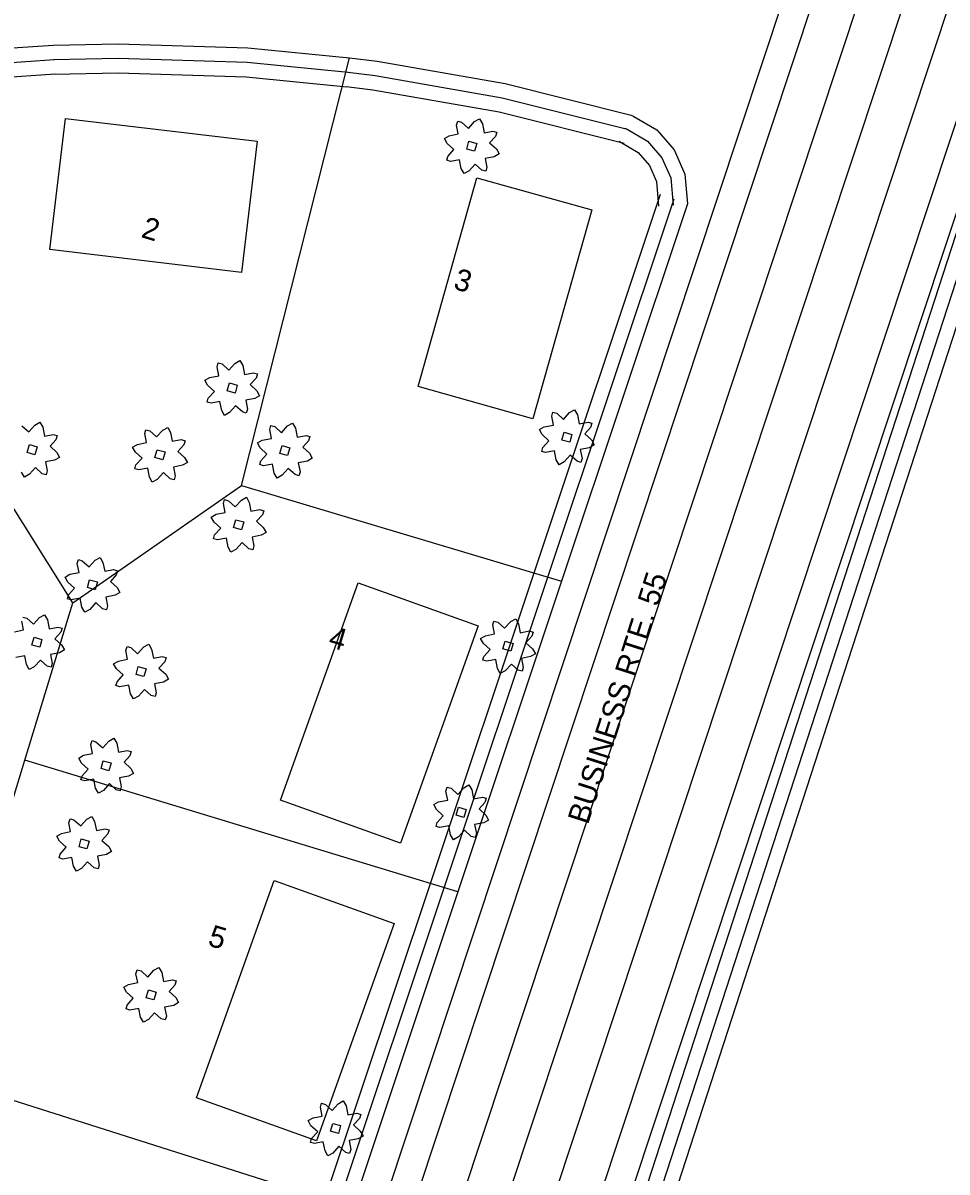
# Model space of a CAD drawing. Extents: x 1810019 to 1811399, y 1074962 to 1076105.
# Drawn here: x 1810680 to 1810935.4, y 1075531.7 to 1075849.4 of the extents above; entities that cross this region are included whole.
import ezdxf

# ---------------------------------------------------------------- set-up
doc = ezdxf.new("R2010")
doc.units = 0
for name, color, linetype in [('Environmental-New trees', 7, 'Continuous'), ('Property-Buildings', 7, 'Continuous'), ('Roadway-Centerline main', 7, 'Continuous'), ('Roadway-Edge of pavement', 7, 'Continuous'), ('Roadway-Edge of shoulder', 7, 'Continuous'), ('Roadway-Land lines', 7, 'Continuous'), ('Roadway-Sidewalks', 7, 'Continuous'), ('Text-Property owner', 7, 'Continuous'), ('Text-Route label', 7, 'Continuous')]:
    doc.layers.add(name, color=color, linetype=linetype)

msp = doc.modelspace()

# ---------------------------------------------------------------- linework, layer by layer
at = {"layer": 'Environmental-New trees'}
for points in [[(1810797.1, 1075811.43), (1810797.41, 1075812.51), (1810799.1, 1075814.37), (1810797.24, 1075816.07), (1810796.46, 1075817.45), (1810797.81, 1075818.21), (1810800.32, 1075818.71), (1810799.85, 1075821.18), (1810800.15, 1075822.26), (1810801.23, 1075821.95), (1810803.1, 1075820.26), (1810804.79, 1075822.12), (1810806.18, 1075822.9), (1810806.96, 1075821.51), (1810807.43, 1075819.04), (1810809.9, 1075819.51), (1810810.98, 1075819.21), (1810810.61, 1075818.05), (1810808.98, 1075816.26), (1810810.85, 1075814.57), (1810811.62, 1075813.18), (1810810.27, 1075812.42), (1810807.76, 1075811.93), (1810808.24, 1075809.46), (1810807.93, 1075808.38), (1810806.85, 1075808.68), (1810804.99, 1075810.38), (1810803.29, 1075808.51), (1810801.91, 1075807.74), (1810801.13, 1075809.12), (1810800.65, 1075811.6), (1810798.18, 1075811.12)], [(1810803.26, 1075816.71), (1810805.43, 1075816.1), (1810804.82, 1075813.93), (1810802.65, 1075814.54)], [(1810730.87, 1075744.59), (1810731.18, 1075745.67), (1810732.87, 1075747.53), (1810731.01, 1075749.23), (1810730.23, 1075750.62), (1810731.59, 1075751.37), (1810734.09, 1075751.87), (1810733.62, 1075754.34), (1810733.93, 1075755.42), (1810735.01, 1075755.12), (1810736.87, 1075753.42), (1810738.56, 1075755.28), (1810739.95, 1075756.06), (1810740.73, 1075754.67), (1810741.2, 1075752.2), (1810743.67, 1075752.67), (1810744.76, 1075752.37), (1810744.39, 1075751.21), (1810742.76, 1075749.42), (1810744.62, 1075747.73), (1810745.4, 1075746.34), (1810744.04, 1075745.59), (1810741.54, 1075745.09), (1810742.01, 1075742.62), (1810741.7, 1075741.54), (1810740.62, 1075741.84), (1810738.76, 1075743.54), (1810737.07, 1075741.68), (1810735.68, 1075740.9), (1810734.9, 1075742.29), (1810734.43, 1075744.76), (1810731.96, 1075744.28)], [(1810737.04, 1075749.87), (1810739.2, 1075749.26), (1810738.59, 1075747.09), (1810736.43, 1075747.7)], [(1810823.38, 1075730.96), (1810823.68, 1075732.05), (1810825.38, 1075733.91), (1810823.52, 1075735.6), (1810822.74, 1075736.99), (1810824.09, 1075737.75), (1810826.6, 1075738.24), (1810826.13, 1075740.71), (1810826.43, 1075741.79), (1810827.51, 1075741.49), (1810829.38, 1075739.8), (1810831.07, 1075741.66), (1810832.46, 1075742.43), (1810833.23, 1075741.05), (1810833.71, 1075738.58), (1810836.18, 1075739.05), (1810837.26, 1075738.74), (1810836.89, 1075737.59), (1810835.26, 1075735.8), (1810837.12, 1075734.11), (1810837.9, 1075732.72), (1810836.55, 1075731.96), (1810834.04, 1075731.47), (1810834.52, 1075728.99), (1810834.21, 1075727.91), (1810833.13, 1075728.22), (1810831.27, 1075729.91), (1810829.57, 1075728.05), (1810828.18, 1075727.27), (1810827.41, 1075728.66), (1810826.93, 1075731.13), (1810824.46, 1075730.66)], [(1810710.91, 1075726.12), (1810711.21, 1075727.2), (1810712.91, 1075729.06), (1810711.04, 1075730.76), (1810710.27, 1075732.15), (1810711.62, 1075732.9), (1810714.13, 1075733.4), (1810713.65, 1075735.87), (1810713.96, 1075736.95), (1810715.04, 1075736.65), (1810716.9, 1075734.95), (1810718.6, 1075736.81), (1810719.98, 1075737.59), (1810720.76, 1075736.2), (1810721.24, 1075733.73), (1810723.71, 1075734.2), (1810724.79, 1075733.9), (1810724.42, 1075732.74), (1810722.79, 1075730.96), (1810724.65, 1075729.26), (1810725.43, 1075727.87), (1810724.08, 1075727.12), (1810721.57, 1075726.62), (1810722.04, 1075724.15), (1810721.74, 1075723.07), (1810720.66, 1075723.37), (1810718.79, 1075725.07), (1810717.1, 1075723.21), (1810715.71, 1075722.43), (1810714.93, 1075723.82), (1810714.46, 1075726.29), (1810711.99, 1075725.81)], [(1810745.42, 1075727.28), (1810745.73, 1075728.36), (1810747.42, 1075730.22), (1810745.56, 1075731.92), (1810744.78, 1075733.3), (1810746.13, 1075734.06), (1810748.64, 1075734.55), (1810748.17, 1075737.03), (1810748.47, 1075738.11), (1810749.56, 1075737.8), (1810751.42, 1075736.11), (1810753.11, 1075737.97), (1810754.5, 1075738.75), (1810755.28, 1075737.36), (1810755.75, 1075734.89), (1810758.22, 1075735.36), (1810759.3, 1075735.06), (1810758.93, 1075733.9), (1810757.3, 1075732.11), (1810759.17, 1075730.42), (1810759.94, 1075729.03), (1810758.59, 1075728.27), (1810756.08, 1075727.78), (1810756.56, 1075725.31), (1810756.25, 1075724.23), (1810755.17, 1075724.53), (1810753.31, 1075726.22), (1810751.61, 1075724.36), (1810750.23, 1075723.59), (1810749.45, 1075724.97), (1810748.98, 1075727.45), (1810746.5, 1075726.97)], [(1810829.54, 1075736.24), (1810831.71, 1075735.63), (1810831.1, 1075733.46), (1810828.93, 1075734.07)], [(1810681.73, 1075732.81), (1810683.89, 1075732.2), (1810683.28, 1075730.03), (1810681.12, 1075730.64)], [(1810717.07, 1075731.4), (1810719.24, 1075730.79), (1810718.63, 1075728.62), (1810716.46, 1075729.23)], [(1810751.58, 1075732.56), (1810753.75, 1075731.95), (1810753.14, 1075729.78), (1810750.97, 1075730.39)], [(1810732.65, 1075706.78), (1810732.96, 1075707.86), (1810734.65, 1075709.72), (1810732.79, 1075711.42), (1810732.01, 1075712.81), (1810733.36, 1075713.56), (1810735.87, 1075714.06), (1810735.4, 1075716.53), (1810735.7, 1075717.61), (1810736.79, 1075717.31), (1810738.65, 1075715.61), (1810740.34, 1075717.47), (1810741.73, 1075718.25), (1810742.51, 1075716.86), (1810742.98, 1075714.39), (1810745.45, 1075714.86), (1810746.54, 1075714.56), (1810746.17, 1075713.4), (1810744.54, 1075711.62), (1810746.4, 1075709.92), (1810747.18, 1075708.53), (1810745.82, 1075707.78), (1810743.32, 1075707.28), (1810743.79, 1075704.81), (1810743.48, 1075703.73), (1810742.4, 1075704.03), (1810740.54, 1075705.73), (1810738.85, 1075703.87), (1810737.46, 1075703.09), (1810736.68, 1075704.48), (1810736.21, 1075706.95), (1810733.74, 1075706.48)], [(1810738.82, 1075712.06), (1810740.98, 1075711.45), (1810740.37, 1075709.28), (1810738.21, 1075709.89)], [(1810692.24, 1075690.19), (1810692.54, 1075691.27), (1810694.24, 1075693.13), (1810692.37, 1075694.82), (1810691.6, 1075696.21), (1810692.95, 1075696.97), (1810695.46, 1075697.46), (1810694.98, 1075699.93), (1810695.29, 1075701.02), (1810696.37, 1075700.71), (1810698.23, 1075699.02), (1810699.93, 1075700.88), (1810701.31, 1075701.66), (1810702.09, 1075700.27), (1810702.56, 1075697.8), (1810705.04, 1075698.27), (1810706.12, 1075697.97), (1810705.75, 1075696.81), (1810704.12, 1075695.02), (1810705.98, 1075693.33), (1810706.76, 1075691.94), (1810705.41, 1075691.18), (1810702.9, 1075690.69), (1810703.37, 1075688.22), (1810703.07, 1075687.13), (1810701.98, 1075687.44), (1810700.12, 1075689.13), (1810698.43, 1075687.27), (1810697.04, 1075686.49), (1810696.26, 1075687.88), (1810695.79, 1075690.35), (1810693.32, 1075689.88)], [(1810698.4, 1075695.46), (1810700.57, 1075694.85), (1810699.96, 1075692.69), (1810697.79, 1075693.3)], [(1810807.11, 1075673.21), (1810807.41, 1075674.29), (1810809.11, 1075676.16), (1810807.25, 1075677.85), (1810806.47, 1075679.24), (1810807.82, 1075680), (1810810.33, 1075680.49), (1810809.86, 1075682.96), (1810810.16, 1075684.04), (1810811.24, 1075683.74), (1810813.1, 1075682.04), (1810814.8, 1075683.91), (1810816.19, 1075684.68), (1810816.96, 1075683.29), (1810817.44, 1075680.82), (1810819.91, 1075681.3), (1810820.99, 1075680.99), (1810820.62, 1075679.83), (1810818.99, 1075678.05), (1810820.85, 1075676.35), (1810821.63, 1075674.97), (1810820.28, 1075674.21), (1810817.77, 1075673.71), (1810818.24, 1075671.24), (1810817.94, 1075670.16), (1810816.86, 1075670.47), (1810815, 1075672.16), (1810813.3, 1075670.3), (1810811.91, 1075669.52), (1810811.14, 1075670.91), (1810810.66, 1075673.38), (1810808.19, 1075672.91)], [(1810683.05, 1075679.58), (1810685.21, 1075678.97), (1810684.6, 1075676.8), (1810682.44, 1075677.41)], [(1810705.68, 1075666.19), (1810705.98, 1075667.27), (1810707.68, 1075669.13), (1810705.82, 1075670.83), (1810705.04, 1075672.22), (1810706.39, 1075672.97), (1810708.9, 1075673.47), (1810708.42, 1075675.94), (1810708.73, 1075677.02), (1810709.81, 1075676.72), (1810711.67, 1075675.02), (1810713.37, 1075676.88), (1810714.76, 1075677.66), (1810715.53, 1075676.27), (1810716.01, 1075673.8), (1810718.48, 1075674.28), (1810719.56, 1075673.97), (1810719.19, 1075672.81), (1810717.56, 1075671.03), (1810719.42, 1075669.33), (1810720.2, 1075667.94), (1810718.85, 1075667.19), (1810716.34, 1075666.69), (1810716.81, 1075664.22), (1810716.51, 1075663.14), (1810715.43, 1075663.44), (1810713.56, 1075665.14), (1810711.87, 1075663.28), (1810710.48, 1075662.5), (1810709.71, 1075663.89), (1810709.23, 1075666.36), (1810706.76, 1075665.89)], [(1810813.27, 1075678.49), (1810815.44, 1075677.88), (1810814.83, 1075675.71), (1810812.66, 1075676.32)], [(1810711.84, 1075671.47), (1810714.01, 1075670.86), (1810713.4, 1075668.69), (1810711.23, 1075669.3)], [(1810696.01, 1075640.16), (1810696.32, 1075641.24), (1810698.01, 1075643.1), (1810696.15, 1075644.79), (1810695.37, 1075646.18), (1810696.72, 1075646.94), (1810699.23, 1075647.43), (1810698.76, 1075649.9), (1810699.06, 1075650.99), (1810700.15, 1075650.68), (1810702.01, 1075648.99), (1810703.7, 1075650.85), (1810705.09, 1075651.63), (1810705.87, 1075650.24), (1810706.34, 1075647.77), (1810708.81, 1075648.24), (1810709.89, 1075647.94), (1810709.53, 1075646.78), (1810707.9, 1075644.99), (1810709.76, 1075643.3), (1810710.53, 1075641.91), (1810709.18, 1075641.15), (1810706.68, 1075640.66), (1810707.15, 1075638.19), (1810706.84, 1075637.1), (1810705.76, 1075637.41), (1810703.9, 1075639.1), (1810702.21, 1075637.24), (1810700.82, 1075636.46), (1810700.04, 1075637.85), (1810699.57, 1075640.32), (1810697.1, 1075639.85)], [(1810702.18, 1075645.43), (1810704.34, 1075644.82), (1810703.73, 1075642.66), (1810701.56, 1075643.27)], [(1810794.17, 1075627.27), (1810794.47, 1075628.35), (1810796.16, 1075630.21), (1810794.3, 1075631.91), (1810793.52, 1075633.3), (1810794.88, 1075634.05), (1810797.38, 1075634.55), (1810796.91, 1075637.02), (1810797.22, 1075638.1), (1810798.3, 1075637.8), (1810800.16, 1075636.1), (1810801.85, 1075637.96), (1810803.24, 1075638.74), (1810804.02, 1075637.35), (1810804.49, 1075634.88), (1810806.96, 1075635.35), (1810808.05, 1075635.05), (1810807.68, 1075633.89), (1810806.05, 1075632.11), (1810807.91, 1075630.41), (1810808.69, 1075629.02), (1810807.34, 1075628.27), (1810804.83, 1075627.77), (1810805.3, 1075625.3), (1810805, 1075624.22), (1810803.91, 1075624.52), (1810802.05, 1075626.22), (1810800.36, 1075624.36), (1810798.97, 1075623.58), (1810798.19, 1075624.97), (1810797.72, 1075627.44), (1810795.25, 1075626.97)], [(1810800.33, 1075632.55), (1810802.49, 1075631.94), (1810801.88, 1075629.77), (1810799.72, 1075630.38)], [(1810689.93, 1075618.55), (1810690.23, 1075619.64), (1810691.92, 1075621.5), (1810690.06, 1075623.19), (1810689.29, 1075624.58), (1810690.64, 1075625.34), (1810693.14, 1075625.83), (1810692.67, 1075628.3), (1810692.98, 1075629.38), (1810694.06, 1075629.08), (1810695.92, 1075627.39), (1810697.61, 1075629.25), (1810699, 1075630.02), (1810699.78, 1075628.64), (1810700.25, 1075626.17), (1810702.73, 1075626.64), (1810703.81, 1075626.33), (1810703.44, 1075625.18), (1810701.81, 1075623.39), (1810703.67, 1075621.7), (1810704.45, 1075620.31), (1810703.1, 1075619.55), (1810700.59, 1075619.06), (1810701.06, 1075616.58), (1810700.76, 1075615.5), (1810699.67, 1075615.81), (1810697.81, 1075617.5), (1810696.12, 1075615.64), (1810694.73, 1075614.86), (1810693.95, 1075616.25), (1810693.48, 1075618.72), (1810691.01, 1075618.25)], [(1810696.09, 1075623.83), (1810698.26, 1075623.22), (1810697.64, 1075621.05), (1810695.48, 1075621.66)], [(1810708.46, 1075576.8), (1810708.77, 1075577.88), (1810710.46, 1075579.74), (1810708.6, 1075581.44), (1810707.82, 1075582.83), (1810709.18, 1075583.58), (1810711.68, 1075584.08), (1810711.21, 1075586.55), (1810711.52, 1075587.63), (1810712.6, 1075587.33), (1810714.46, 1075585.63), (1810716.15, 1075587.49), (1810717.54, 1075588.27), (1810718.32, 1075586.88), (1810718.79, 1075584.41), (1810721.26, 1075584.88), (1810722.35, 1075584.58), (1810721.98, 1075583.42), (1810720.35, 1075581.63), (1810722.21, 1075579.94), (1810722.99, 1075578.55), (1810721.63, 1075577.8), (1810719.13, 1075577.3), (1810719.6, 1075574.83), (1810719.3, 1075573.75), (1810718.21, 1075574.05), (1810716.35, 1075575.75), (1810714.66, 1075573.89), (1810713.27, 1075573.11), (1810712.49, 1075574.5), (1810712.02, 1075576.97), (1810709.55, 1075576.49)], [(1810714.63, 1075582.08), (1810716.79, 1075581.47), (1810716.18, 1075579.3), (1810714.02, 1075579.91)], [(1810759.45, 1075539.9), (1810759.75, 1075540.98), (1810761.45, 1075542.84), (1810759.59, 1075544.53), (1810758.81, 1075545.92), (1810760.16, 1075546.68), (1810762.67, 1075547.17), (1810762.19, 1075549.64), (1810762.5, 1075550.73), (1810763.58, 1075550.42), (1810765.44, 1075548.73), (1810767.14, 1075550.59), (1810768.53, 1075551.37), (1810769.3, 1075549.98), (1810769.78, 1075547.51), (1810772.25, 1075547.98), (1810773.33, 1075547.67), (1810772.96, 1075546.52), (1810771.33, 1075544.73), (1810773.19, 1075543.04), (1810773.97, 1075541.65), (1810772.62, 1075540.89), (1810770.11, 1075540.4), (1810770.58, 1075537.93), (1810770.28, 1075536.84), (1810769.2, 1075537.15), (1810767.33, 1075538.84), (1810765.64, 1075536.98), (1810764.25, 1075536.2), (1810763.48, 1075537.59), (1810763, 1075540.06), (1810760.53, 1075539.59)], [(1810765.61, 1075545.17), (1810767.78, 1075544.56), (1810767.17, 1075542.4), (1810765, 1075543.01)]]:
    msp.add_lwpolyline(points, close=True, dxfattribs=at)
for points in [[(1810679.7, 1075738.05), (1810681.56, 1075736.36), (1810683.25, 1075738.22), (1810684.64, 1075739), (1810685.42, 1075737.61), (1810685.89, 1075735.14), (1810688.36, 1075735.61), (1810689.45, 1075735.31), (1810689.08, 1075734.15), (1810687.45, 1075732.36), (1810689.31, 1075730.67), (1810690.09, 1075729.28), (1810688.73, 1075728.52), (1810686.23, 1075728.03), (1810686.7, 1075725.56), (1810686.39, 1075724.48), (1810685.31, 1075724.78), (1810683.45, 1075726.48), (1810681.76, 1075724.61), (1810680.37, 1075723.84), (1810679.59, 1075725.22)], [(1810679.94, 1075685.13), (1810681.02, 1075684.83), (1810682.88, 1075683.14), (1810684.57, 1075685), (1810685.96, 1075685.77), (1810686.74, 1075684.39), (1810687.21, 1075681.91), (1810689.68, 1075682.39), (1810690.77, 1075682.08), (1810690.4, 1075680.93), (1810688.77, 1075679.14), (1810690.63, 1075677.45), (1810691.41, 1075676.06), (1810690.06, 1075675.3), (1810687.55, 1075674.81), (1810688.02, 1075672.33), (1810687.72, 1075671.25), (1810686.63, 1075671.56), (1810684.77, 1075673.25), (1810683.08, 1075671.39), (1810681.69, 1075670.61), (1810680.91, 1075672), (1810680.44, 1075674.47), (1810677.97, 1075674)], [(1810677.6, 1075681.09), (1810680.1, 1075681.58), (1810679.63, 1075684.05)]]:
    msp.add_lwpolyline(points, dxfattribs=at)
at = {"layer": 'Property-Buildings'}
for points in [[(1810691.72, 1075823.01), (1810744.7, 1075816.71), (1810740.38, 1075780.43), (1810687.4, 1075786.74)], [(1810805.48, 1075806.62), (1810837.2, 1075797.69), (1810820.93, 1075739.93), (1810789.21, 1075748.87)], [(1810805.79, 1075682.73), (1810784.29, 1075622.65), (1810751.12, 1075634.52), (1810772.63, 1075694.61)], [(1810782.6, 1075600.43), (1810761.1, 1075540.35), (1810727.93, 1075552.22), (1810749.44, 1075612.3)]]:
    msp.add_lwpolyline(points, close=True, dxfattribs=at)
at = {"layer": 'Roadway-Centerline main'}
msp.add_line((1811006.18, 1076104.35), (1810632.15, 1074976.37), dxfattribs=at)
at = {"layer": 'Roadway-Edge of pavement'}
for p, q in [((1810980.71, 1076103.81), (1810606.02, 1074973.81)), ((1810993.45, 1076104.08), (1810619.08, 1074975.09)), ((1811018.91, 1076104.62), (1810645.22, 1074977.65)), ((1811031.64, 1076104.89), (1810658.29, 1074978.93))]:
    msp.add_line(p, q, dxfattribs=at)
at = {"layer": 'Roadway-Edge of shoulder'}
for p, q in [((1811040.13, 1076105.07), (1810667, 1074979.79)), ((1810972.23, 1076103.63), (1810597.31, 1074972.96))]:
    msp.add_line(p, q, dxfattribs=at)
at = {"layer": 'Roadway-Land lines'}
for p, q in [((1810671.71, 1075842.13), (1810688.34, 1075843.28)), ((1810740.41, 1075721.54), (1810770.27, 1075839.75)), ((1810946.95, 1075819.07), (1810694.59, 1075041.79)), ((1810863.66, 1075799.4), (1810828.84, 1075695.06)), ((1810693.76, 1075689.12), (1810662.76, 1075738.45)), ((1810693.76, 1075689.12), (1810740.41, 1075721.54)), ((1810740.41, 1075721.54), (1810828.84, 1075695.06)), ((1810828.84, 1075695.06), (1810800.18, 1075609.17)), ((1810680.49, 1075645.61), (1810693.76, 1075689.12)), ((1810664.7, 1075593.84), (1810680.49, 1075645.61)), ((1810800.18, 1075609.17), (1810680.49, 1075645.61)), ((1810800.18, 1075609.17), (1810771, 1075521.77)), ((1810771, 1075521.77), (1810654.04, 1075558.89))]:
    msp.add_line(p, q, dxfattribs=at)
for points in [[(1810688.34, 1075843.28), (1810706.29, 1075843.66), (1810742.17, 1075842.51), (1810770.27, 1075839.75)], [(1810770.27, 1075839.75), (1810777.88, 1075838.83), (1810813.24, 1075832.63), (1810848.07, 1075823.94)], [(1810848.07, 1075823.94), (1810848.84, 1075823.58), (1810855.16, 1075819.85), (1810860.02, 1075814.31), (1810862.97, 1075807.55), (1810863.66, 1075799.4)]]:
    msp.add_lwpolyline(points, dxfattribs=at)
at = {"layer": 'Roadway-Sidewalks'}
for p, q in [((1810671.99, 1075838.14), (1810688.62, 1075839.29)), ((1810672.26, 1075834.15), (1810688.89, 1075835.3)), ((1810949.56, 1075814.15), (1810700.07, 1075045.72)), ((1810952.49, 1075810.24), (1810705.56, 1075049.66)), ((1810856.07, 1075801.93), (1810821.25, 1075697.59)), ((1810859.87, 1075800.67), (1810825.05, 1075696.33)), ((1810821.25, 1075697.59), (1810792.59, 1075611.71)), ((1810825.05, 1075696.33), (1810796.38, 1075610.44)), ((1810792.59, 1075611.71), (1810763.42, 1075524.3)), ((1810796.38, 1075610.44), (1810767.21, 1075523.03))]:
    msp.add_line(p, q, dxfattribs=at)
for points in [[(1810688.42, 1075839.28), (1810706.27, 1075839.65), (1810741.91, 1075838.52), (1810769.88, 1075835.77)], [(1810688.51, 1075835.28), (1810706.24, 1075835.65), (1810741.65, 1075834.52), (1810769.49, 1075831.78)], [(1810769.79, 1075835.78), (1810777.29, 1075834.87), (1810812.41, 1075828.71), (1810847.11, 1075820.06)], [(1810769.31, 1075831.8), (1810776.71, 1075830.91), (1810811.58, 1075824.8), (1810846.14, 1075816.18)], [(1810846.37, 1075820.33), (1810846.96, 1075820.05), (1810852.57, 1075816.73), (1810856.6, 1075812.14), (1810859.04, 1075806.56), (1810859.68, 1075799.06)], [(1810844.66, 1075816.71), (1810845.09, 1075816.51), (1810849.99, 1075813.61), (1810853.19, 1075809.97), (1810855.11, 1075805.56), (1810855.69, 1075798.72)]]:
    msp.add_lwpolyline(points, dxfattribs=at)

# ---------------------------------------------------------------- texts
at = {"layer": 'Text-Property owner'}
for s, p in [('2', (1810712.37, 1075790.23)), ('3', (1810798.67, 1075775.98)), ('4', (1810764.1, 1075677.03)), ('5', (1810730.8, 1075594.43))]:
    msp.add_text(s, height=6, rotation=343.3561, dxfattribs=at).set_placement(p)
at = {"layer": 'Text-Route label'}
msp.add_text('BUSINESS RTE. 55', height=6, rotation=72.2395, dxfattribs=at).set_placement((1810836.14, 1075627.54))

doc.saveas('drawing.dxf')
